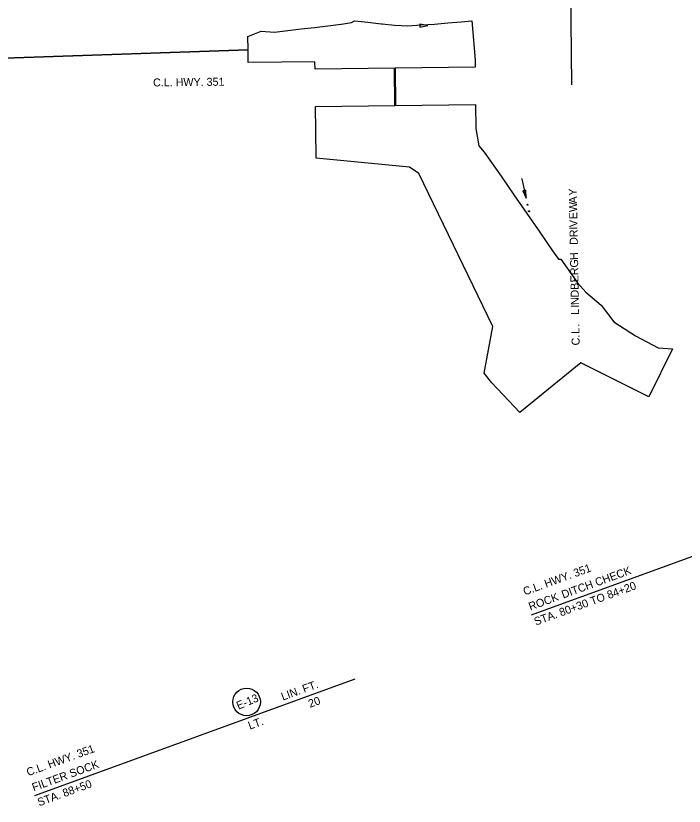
# Model space of a CAD drawing. Extents: x 1710782 to 1712392, y 548480 to 549912.
# Drawn here: x 1711316 to 1711817, y 548672 to 549264 of the extents above; entities that cross this region are included whole.
import ezdxf

# ---------------------------------------------------------------- set-up
doc = ezdxf.new("R2010")
doc.units = 0
for name, color, linetype in [('R_Contours', 7, 'Continuous'), ('R_Erosion_STG 2', 7, 'Continuous'), ('R_Horz Alg Annot', 7, 'Continuous'), ('R_MOT', 7, 'Continuous'), ('R_Water', 7, 'Continuous')]:
    doc.layers.add(name, color=color, linetype=linetype)

msp = doc.modelspace()

# ---------------------------------------------------------------- linework, layer by layer
at = {"layer": 'R_Contours'}
msp.add_lwpolyline([(1711733, 549212.35), (1711731.65, 549332.35)], dxfattribs=at)
at = {"layer": 'R_Erosion_STG 2'}
msp.add_circle((1711489.29, 548749.88), 10.32, dxfattribs=at)
at = {"layer": 'R_Horz Alg Annot'}
for p, q in [((1711702.78, 548815.25), (1711942.84, 548902.62)), ((1711330.63, 548679.79), (1711570.68, 548767.16))]:
    msp.add_line(p, q, dxfattribs=at)
at = {"layer": 'R_MOT'}
for p, q in [((1711658.03, 549260.25), (1711660.49, 549231.04)), ((1711490.29, 549248.71), (1711500.24, 549252.66)), ((1711490.4, 549238.92), (1711490.29, 549248.71)), ((1711490.51, 549229.13), (1711490.4, 549238.42)), ((1711540.5, 549229.7), (1711490.51, 549229.13)), ((1711600.37, 549196.87), (1711600.06, 549224.86)), ((1711600.56, 549224.87), (1711600.87, 549196.87)), ((1711541.31, 549157.31), (1711541.08, 549178.2)), ((1711661.07, 549179.55), (1711663.44, 549166.72)), ((1711611.39, 549150.72), (1711541.31, 549157.31)), ((1711618.32, 549145.81), (1711611.39, 549150.72)), ((1711673.91, 549031.19), (1711618.32, 549145.81)), ((1711667.23, 548996.21), (1711673.91, 549031.19)), ((1711673.91, 549031.19), (1711673.91, 549031.19)), ((1711673.12, 548989.04), (1711667.23, 548996.21))]:
    msp.add_line(p, q, dxfattribs=at)
for points in [[(1711500.24, 549252.66), (1711510.25, 549251.89), (1711520.24, 549253.04), (1711530.23, 549254.23), (1711540.21, 549255.46), (1711550.2, 549256.67), (1711560.19, 549257.88), (1711561.84, 549258.13), (1711561.85, 549258.13), (1711567.8, 549259.07), (1711570.16, 549260.38), (1711580.17, 549259.31), (1711590.19, 549258.2), (1711590.77, 549258.15), (1711600.2, 549257.08), (1711610.21, 549256.49), (1711620.2, 549257.29), (1711630.19, 549257.9), (1711640.18, 549258.81), (1711650.17, 549259.58), (1711658.03, 549260.25)], [(1711306.31, 549234.47), (1711308.1, 549232.55), (1711490.4, 549238.92)], [(1711490.4, 549238.42), (1711307.77, 549232.03), (1711306.38, 549233.97)], [(1711660.49, 549231.04), (1711660.56, 549225.54), (1711600.56, 549224.87)], [(1711600.06, 549224.86), (1711540.56, 549224.2), (1711540.5, 549229.7)], [(1711541.08, 549178.2), (1711540.88, 549196.2), (1711600.37, 549196.87)], [(1711600.87, 549196.87), (1711660.87, 549197.54), (1711661.07, 549179.55)], [(1711663.44, 549166.72), (1711667.27, 549161.8), (1711679.95, 549144.01), (1711689.62, 549129.98), (1711699.3, 549115.95), (1711708.97, 549101.92), (1711718.65, 549087.89), (1711723.01, 549081.72), (1711724.77, 549081.73), (1711737.29, 549064.07), (1711743.56, 549057.03), (1711754.93, 549047.27), (1711764.61, 549034.78), (1711780.72, 549024.22), (1711797.83, 549015.34), (1711808.51, 549014.46)], [(1711808.51, 549014.46), (1711790.7, 548978.65), (1711739.66, 549004.03), (1711694.14, 548966.7), (1711673.12, 548989.04)]]:
    msp.add_lwpolyline(points, dxfattribs=at)
at = {"layer": 'R_Water'}
for p, q in [((1711625.19, 549256.96), (1711619.16, 549257.83)), ((1711619.16, 549257.83), (1711619.22, 549255.72)), ((1711619.22, 549255.72), (1711625.19, 549256.96)), ((1711698.49, 549133.5), (1711696.42, 549133.04)), ((1711696.42, 549133.04), (1711698.74, 549127.41)), ((1711698.74, 549127.41), (1711698.49, 549133.5))]:
    msp.add_line(p, q, dxfattribs=at)
for points in [[(1711695.53, 549142.06), (1711695.63, 549141.62), (1711698.74, 549127.41)], [(1711701.94, 549112.76), (1711701.95, 549112.72)]]:
    msp.add_lwpolyline(points, dxfattribs=at)
for centre in [(1711699.84, 549122.53), (1711700.91, 549117.63)]:
    msp.add_circle(centre, 0.375, dxfattribs=at)

# ---------------------------------------------------------------- texts
at = {"layer": 'R_Erosion_STG 2'}
msp.add_text('E-13', height=5.999, rotation=22.76012, dxfattribs=at).set_placement((1711483.15, 548744.05))
at = {"layer": 'R_Horz Alg Annot'}
for s, rotation, p in [('C.L. HWY. 351', 0.64281, (1711419.21, 549211.14)), ('Y', 91.07865, (1711736.79, 549129.36)), ('A', 91.07865, (1711736.9, 549123.5)), ('W', 91.07865, (1711737.02, 549117.08)), ('E', 91.07865, (1711737.12, 549111.7)), ('V', 91.07865, (1711737.23, 549105.84)), ('I', 91.07865, (1711737.27, 549103.85)), ('R', 91.07865, (1711737.38, 549098.19)), ('D', 91.07865, (1711737.48, 549092.52)), ('H', 91.07865, (1711737.7, 549081.13)), ('G', 91.07865, (1711737.8, 549075.47)), ('R', 91.07865, (1711737.91, 549069.8)), ('E', 91.07865, (1711738.01, 549064.41)), ('B', 91.07865, (1711738.12, 549058.74)), ('D', 91.07865, (1711738.23, 549053.08)), ('N', 91.07865, (1711738.33, 549047.41)), ('I', 91.07865, (1711738.37, 549045.42)), ('L', 91.07865, (1711738.47, 549040.04)), ('L', 91.07865, (1711738.74, 549025.73)), ('.', 91.07865, (1711738.64, 549031.11)), ('.', 91.07865, (1711738.8, 549022.8)), ('C', 91.07865, (1711738.9, 549017.13)), ('C.L. HWY. 351', 20, (1711697.8, 548829.62)), (' DITCH CHECK', 20, (1711724.46, 548826.55)), ('STA. 80+30 TO 84+20', 20, (1711706.01, 548807.07)), ('ROCK', 20, (1711701.91, 548818.34)), ('   LIN. FT. ', 20, (1711510.17, 548748.56)), ('20', 20, (1711536.82, 548745.49)), ('LT.', 20, (1711491.72, 548729.07)), ('C.L. HWY. 351', 20, (1711325.64, 548694.17)), ('FILTER SOCK', 20, (1711329.75, 548682.89)), ('STA. 88+50', 20, (1711333.85, 548671.61))]:
    msp.add_text(s, height=6, rotation=rotation, dxfattribs=at).set_placement(p)

doc.saveas('drawing.dxf')
